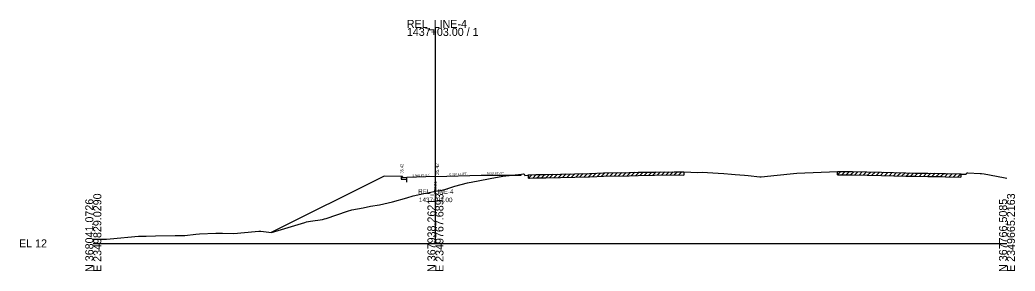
# Model space of a CAD drawing. Extents: x -26 to 2350146, y -10 to 368200.
# Drawn here: x 974.3 to 1322.6, y 8990.3 to 9078.2 of the extents above; entities that cross this region are included whole.
import ezdxf

# ---------------------------------------------------------------- set-up
doc = ezdxf.new("R2010")
doc.units = 0
for name, color, linetype in [('RD_GPK_XS_Cell', 7, 'Continuous'), ('RD_XS_CurbBase', 7, 'Continuous'), ('RD_XS_CurbFront', 7, 'Continuous'), ('RD_XS_CurbTop', 7, 'Continuous'), ('RD_XS_EarthShd', 7, 'Continuous'), ('RD_XS_ExGround', 7, 'Continuous'), ('RD_XS_ExPaveRet', 7, 'Continuous'), ('RD_XS_MatchLine', 7, 'Continuous'), ('RD_XS_Pave', 7, 'Continuous'), ('RD_XS_PaveShd', 7, 'Continuous'), ('RD_XS_TieSlope', 7, 'Continuous'), ('RD_XS_TX_Elev_EX', 7, 'Continuous'), ('RD_XS_TX_Elev_PR', 7, 'Continuous'), ('RD_XS_TX_Slope', 7, 'Continuous'), ('RD_XS_TX_Station', 7, 'Continuous'), ('RD_XS_TX_TOC', 7, 'Continuous')]:
    doc.layers.add(name, color=color, linetype=linetype)

msp = doc.modelspace()

# ---------------------------------------------------------------- linework, layer by layer
at = {"layer": 'RD_GPK_XS_Cell'}
for p, q in [((1119.72, 9000), (1119.72, 9075.38)), ((1000, 9000), (1119.72, 9000)), ((1119.72, 9000), (1319.72, 9000))]:
    msp.add_line(p, q, dxfattribs=at)
at = {"layer": 'RD_XS_CurbBase'}
for p, q in [((1107.72, 9023.42), (1107.72, 9022.42)), ((1107.72, 9022.42), (1108.22, 9022.42)), ((1108.22, 9022.42), (1109.72, 9022.5)), ((1109.72, 9021.44), (1109.72, 9022.5))]:
    msp.add_line(p, q, dxfattribs=at)
at = {"layer": 'RD_XS_CurbFront'}
msp.add_line((1109.72, 9022.5), (1109.72, 9023), dxfattribs=at)
at = {"layer": 'RD_XS_CurbTop'}
for p, q in [((1108.22, 9023.42), (1107.72, 9023.42)), ((1108.3, 9022.92), (1108.22, 9023.42)), ((1109.72, 9023), (1108.3, 9022.92)), ((1109.72, 9023.02), (1109.72, 9023))]:
    msp.add_line(p, q, dxfattribs=at)
at = {"layer": 'RD_XS_EarthShd'}
for p, q in [((1107.72, 9023.42), (1101.72, 9023.54)), ((1145.72, 9023.88), (1149.72, 9023.89))]:
    msp.add_line(p, q, dxfattribs=at)
at = {"layer": 'RD_XS_ExGround'}
msp.add_lwpolyline([(1000, 9001.48), (1002.71, 9001.42), (1004.66, 9001.51), (1005.85, 9001.56), (1015.83, 9002.52), (1018.46, 9002.5), (1021.8, 9002.6), (1028.64, 9002.76), (1032.04, 9002.72), (1035.84, 9003.25), (1037.2, 9003.39), (1042.89, 9003.55), (1045.17, 9003.54), (1049.13, 9003.5), (1056.6, 9004.2), (1057.94, 9004.25), (1058.63, 9004.27), (1062.31, 9003.82), (1074, 9007.32), (1074.61, 9007.5), (1075.96, 9007.72), (1080.21, 9008.37), (1080.85, 9008.54), (1081.44, 9008.69), (1089, 9011.24), (1090.45, 9011.68), (1094.44, 9012.49), (1096.98, 9012.98), (1100.09, 9013.48), (1104.72, 9014.58), (1109.65, 9015.99), (1111.89, 9016.64), (1115.69, 9017.47), (1117.54, 9017.83), (1119.72, 9018.24), (1122.6, 9018.78), (1126.49, 9020.01), (1130.95, 9021.14), (1134.65, 9021.92), (1138.86, 9022.74), (1143.35, 9023.5), (1149.79, 9024.24), (1150.39, 9024.29), (1150.82, 9024.27), (1150.97, 9023.78), (1152.02, 9023.84), (1152.29, 9023.95), (1152.67, 9023.96), (1154.87, 9024.04), (1158.36, 9024.12), (1173.68, 9024.46), (1176.2, 9024.56), (1178.54, 9024.64), (1187.55, 9024.82), (1190.66, 9024.89), (1196.35, 9024.97), (1203.24, 9025.08), (1203.7, 9025.07), (1206.6, 9025.02), (1211.48, 9024.81), (1213.06, 9024.94), (1218.71, 9024.55), (1220.59, 9024.5), (1223.33, 9024.25), (1224.55, 9024.15), (1227.91, 9023.83), (1229.19, 9023.71), (1233.27, 9023.29), (1233.71, 9023.24), (1239.3, 9023.9), (1245.04, 9024.5), (1246.17, 9024.55), (1260.45, 9025.1), (1263.14, 9025.12), (1263.68, 9025.13), (1265.66, 9025.09), (1275.76, 9024.89), (1284.37, 9024.69), (1287.53, 9024.61), (1292.01, 9024.55), (1297, 9024.48), (1298.21, 9024.45), (1303.57, 9024.29), (1303.77, 9024.22), (1304.82, 9024.2), (1305.47, 9024.18), (1305.65, 9024.64), (1306.03, 9024.65), (1310.36, 9024.49), (1310.79, 9024.49), (1311.73, 9024.28), (1318.52, 9023), (1319.72, 9022.81)], dxfattribs=at)
at = {"layer": 'RD_XS_ExPaveRet'}
for p, q in [((1152.29, 9022.8), (1153.47, 9023.99)), ((1152.29, 9022.8), (1152.29, 9023.95)), ((1153.79, 9022.86), (1154.97, 9024.04)), ((1155.29, 9022.9), (1156.46, 9024.07)), ((1156.79, 9022.94), (1157.96, 9024.11)), ((1158.29, 9022.97), (1159.46, 9024.14)), ((1158.36, 9022.98), (1173.68, 9023.32)), ((1159.79, 9023.01), (1160.96, 9024.18)), ((1161.29, 9023.04), (1162.46, 9024.21)), ((1162.79, 9023.07), (1163.96, 9024.24)), ((1164.29, 9023.11), (1165.46, 9024.28)), ((1165.79, 9023.14), (1166.96, 9024.31)), ((1167.29, 9023.17), (1168.46, 9024.34)), ((1168.79, 9023.21), (1169.96, 9024.38)), ((1170.29, 9023.24), (1171.46, 9024.41)), ((1171.79, 9023.27), (1172.96, 9024.44)), ((1173.29, 9023.31), (1174.47, 9024.49)), ((1173.68, 9023.32), (1176.2, 9023.41)), ((1174.79, 9023.36), (1175.98, 9024.55)), ((1176.2, 9023.41), (1178.54, 9023.5)), ((1176.29, 9023.42), (1177.47, 9024.6)), ((1177.79, 9023.47), (1178.97, 9024.65)), ((1178.54, 9023.5), (1187.55, 9023.68)), ((1179.29, 9023.51), (1180.45, 9024.68)), ((1180.79, 9023.54), (1181.95, 9024.71)), ((1182.29, 9023.57), (1183.45, 9024.74)), ((1183.79, 9023.6), (1184.95, 9024.77)), ((1185.29, 9023.64), (1186.45, 9024.8)), ((1186.79, 9023.67), (1187.95, 9024.83)), ((1187.55, 9023.68), (1190.66, 9023.74)), ((1188.29, 9023.7), (1189.45, 9024.86)), ((1189.79, 9023.73), (1190.95, 9024.89)), ((1190.66, 9023.74), (1196.35, 9023.83)), ((1191.29, 9023.75), (1192.45, 9024.91)), ((1192.79, 9023.78), (1193.95, 9024.94)), ((1194.29, 9023.8), (1195.45, 9024.96)), ((1195.79, 9023.82), (1196.95, 9024.98)), ((1196.35, 9023.83), (1203.24, 9023.93)), ((1197.29, 9023.84), (1198.45, 9025)), ((1198.79, 9023.87), (1199.95, 9025.03)), ((1200.29, 9023.89), (1201.45, 9025.05)), ((1201.79, 9023.91), (1202.95, 9025.07)), ((1203.24, 9023.93), (1203.7, 9023.93)), ((1203.29, 9023.93), (1204.41, 9025.06)), ((1203.7, 9023.93), (1206.6, 9023.88)), ((1204.79, 9023.91), (1205.91, 9025.03)), ((1206.6, 9025.02), (1206.6, 9023.88)), ((1260.45, 9023.95), (1261.6, 9025.11)), ((1260.45, 9023.95), (1260.45, 9025.1)), ((1260.45, 9023.95), (1263.14, 9023.98)), ((1261.95, 9023.97), (1263.1, 9025.12)), ((1263.14, 9023.98), (1263.68, 9023.98)), ((1263.45, 9023.98), (1264.58, 9025.11)), ((1263.68, 9023.98), (1265.66, 9023.95)), ((1264.95, 9023.96), (1266.07, 9025.08)), ((1265.66, 9023.95), (1275.76, 9023.75)), ((1266.45, 9023.93), (1267.57, 9025.05)), ((1267.95, 9023.9), (1269.07, 9025.02)), ((1269.45, 9023.87), (1270.57, 9024.99)), ((1270.95, 9023.84), (1272.07, 9024.96)), ((1272.45, 9023.81), (1273.57, 9024.93)), ((1273.95, 9023.78), (1275.07, 9024.9)), ((1275.45, 9023.75), (1276.56, 9024.87)), ((1275.76, 9023.75), (1284.37, 9023.54)), ((1276.95, 9023.72), (1278.06, 9024.84)), ((1278.45, 9023.68), (1279.56, 9024.8)), ((1279.95, 9023.65), (1281.06, 9024.76)), ((1281.45, 9023.61), (1282.56, 9024.73)), ((1282.95, 9023.58), (1284.06, 9024.69)), ((1284.37, 9023.54), (1287.53, 9023.47)), ((1284.45, 9023.54), (1285.56, 9024.66)), ((1285.95, 9023.51), (1287.06, 9024.62)), ((1287.45, 9023.47), (1288.57, 9024.6)), ((1287.53, 9023.47), (1292.01, 9023.41)), ((1288.95, 9023.45), (1290.08, 9024.58)), ((1290.45, 9023.43), (1291.58, 9024.56)), ((1291.95, 9023.41), (1293.07, 9024.54)), ((1292.01, 9023.41), (1297, 9023.34)), ((1293.45, 9023.39), (1294.57, 9024.52)), ((1294.95, 9023.37), (1296.07, 9024.49)), ((1296.45, 9023.35), (1297.57, 9024.46)), ((1297, 9023.34), (1298.21, 9023.3)), ((1297.95, 9023.31), (1299.06, 9024.42)), ((1298.21, 9023.3), (1303.57, 9023.15)), ((1299.45, 9023.27), (1300.56, 9024.38)), ((1300.95, 9023.23), (1302.06, 9024.34)), ((1302.45, 9023.18), (1303.56, 9024.3)), ((1303.57, 9024.29), (1303.57, 9023.15)), ((1152.29, 9022.8), (1152.67, 9022.82)), ((1152.67, 9022.82), (1154.87, 9022.89)), ((1154.87, 9022.89), (1158.36, 9022.98))]:
    msp.add_line(p, q, dxfattribs=at)
at = {"layer": 'RD_XS_MatchLine'}
msp.add_line((1149.72, 9023.89), (1149.72, 9024.24), dxfattribs=at)
at = {"layer": 'RD_XS_Pave'}
for q in [(1109.72, 9023.02), (1135.72, 9023.87)]:
    msp.add_line((1119.72, 9023.42), q, dxfattribs=at)
at = {"layer": 'RD_XS_PaveShd'}
msp.add_line((1135.72, 9023.87), (1145.72, 9023.88), dxfattribs=at)
at = {"layer": 'RD_XS_TieSlope'}
msp.add_line((1101.72, 9023.54), (1062.29, 9003.82), dxfattribs=at)

# ---------------------------------------------------------------- texts
at = {"layer": 'RD_GPK_XS_Cell'}
for s, p in [('1437+03.00 / 1', (1109.72, 9072.58)), ('REL_LINE-4', (1109.72, 9075.38)), ('EL 12', (974, 8998.6))]:
    msp.add_text(s, height=2.8, dxfattribs=at).set_placement(p)
for s, p in [('E 2349829.0290', (1002.8, 8990)), ('E 2349767.6893', (1122.52, 8990)), ('E 2349665.2163', (1322.52, 8990)), ('N 368041.0726', (1000, 8990)), ('N 367938.2621', (1119.72, 8990)), ('N 367766.5085', (1319.72, 8990))]:
    msp.add_text(s, height=2.8, rotation=90, dxfattribs=at).set_placement(p)
at = {"layer": 'RD_XS_TX_Elev_EX'}
msp.add_text('30.24', height=1, rotation=90, dxfattribs=at).set_placement((1120.22, 9018.24))
at = {"layer": 'RD_XS_TX_Elev_PR'}
for s, height, p in [('35.42', 1, (1108.47, 9024.42)), (' 35.42', 1.2, (1120.92, 9023.42))]:
    msp.add_text(s, height=height, rotation=90, dxfattribs=at).set_placement(p)
at = {"layer": 'RD_XS_TX_Slope'}
for s, rotation, p in [('0.040 FT./FT.', 2.2906, (1111.68, 9023.35)), ('0.028 FT./FT.', 1.5897, (1124.68, 9023.81)), ('0.002 FT./FT.', 0.087, (1137.69, 9024.12))]:
    msp.add_text(s, height=0.75, rotation=rotation, dxfattribs=at).set_placement(p)
at = {"layer": 'RD_XS_TX_Station'}
for s, p in [('REL_LINE-4', (1113.65, 9017.32)), ('1437+03.00', (1113.95, 9014.42))]:
    msp.add_text(s, height=1.6, dxfattribs=at).set_placement(p)
at = {"layer": 'RD_XS_TX_TOC'}
msp.add_text('TOCLT', height=0.05, dxfattribs=at).set_placement((1108.27, 9023.37))

doc.saveas('drawing.dxf')
